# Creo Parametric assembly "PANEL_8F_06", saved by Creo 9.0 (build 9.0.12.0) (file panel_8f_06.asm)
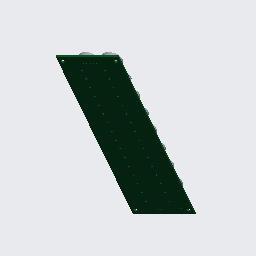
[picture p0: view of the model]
Units: millimeter Newton Second (mmNs); MM, TONNE, SECS

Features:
  1. coordinate system "PANEL_8F_06"
  2. imported feature "Import Feature id 4"
  3. component "PCB_8F"
  4. component "TX_8F_T1"
  5. component "TX_8F_T1"
  6. component "TX_8F_T1"
  7. component "TX_8F_T1"
  8. component "TX_8F_T1"
  9. component "TX_8F_T1"
  10. component "TX_8F_T1"
  11. component "TX_8F_T1"
  12. component "TX_8F_T1"
  13. component "TX_8F_T1"
  14. component "TX_8F_T1"
  15. component "TX_8F_T1"
  16. component "TX_8F_T1"
  17. component "TX_8F_T1"
  18. component "TX_8F_T1"
  19. component "TX_8F_T1"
